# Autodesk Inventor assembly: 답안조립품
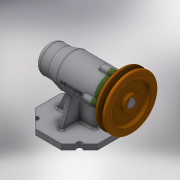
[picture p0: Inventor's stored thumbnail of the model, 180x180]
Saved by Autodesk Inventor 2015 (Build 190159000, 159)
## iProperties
Created: 2019-12
Part Number: 답안조립품
Document SubType Name: Assembly
Designer: SCD-A02
Author: SCD-A02
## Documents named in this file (12)
- C:\Users\SCD-A02\Desktop\491204V1025\답안조립품.iam
- C:\Users\SCD-A02\Desktop\491204V1025\1.본체.ipt
- C:\Users\SCD-A02\Desktop\491204V1025\V벨트풀리.ipt
- C:\Users\SCD-A02\Desktop\491204V1025\멈춤나사 M3.ipt
- C:\Users\SCD-A02\Desktop\491204V1025\베어링 6004.ipt
- C:\Users\SCD-A02\Desktop\491204V1025\베어링 51202.ipt
- C:\Users\SCD-A02\Desktop\491204V1025\볼트 M4.ipt
- C:\Users\SCD-A02\Desktop\491204V1025\어댑터슬리브.ipt
- C:\Users\SCD-A02\Desktop\491204V1025\오일 실.ipt
- C:\Users\SCD-A02\Desktop\491204V1025\축.ipt
- C:\Users\SCD-A02\Desktop\491204V1025\커버.ipt
- C:\Users\SCD-A02\Desktop\491204V1025\키 5 x 5 x 16.ipt
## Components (2 placed, 2 different names)
1. 1.본체:1 — 각도:1
2. V벨트풀리:1 — 각도:3
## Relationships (2: Angle 2)
- 각도:1 [Angle]: 1.본체:1
- 각도:3 [Angle]: V벨트풀리:1
